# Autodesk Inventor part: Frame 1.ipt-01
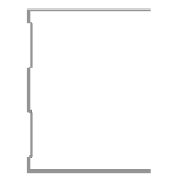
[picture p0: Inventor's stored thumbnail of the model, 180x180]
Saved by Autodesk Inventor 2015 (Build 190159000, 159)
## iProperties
Created: 2015-04
Part Number: Frame 1.ipt-01
Material: Aluminum 6061
Document SubType Name: Modeling
Standard: Unnamed
Designer: suporte
Language: en-US
Size Designation: (Unnamed 1)
Categories: <MemberInstance><Categories><Category DisplayName="Structural Shapes" InternalName="089c4875-fa83-4c05-b084-43b9cc11f5ed" Mnemonic="GRDR"><CategoryParameter Dis
Density: 2.7 g/cm^3
Appearance: Aluminum - Flat
IsCustomPart: 1
G_L: 2100,000 mm
G_W: 70,000 mm
G_H: 75,000 mm
_CCFamilyMember: 1
_CCFamilyDisplayName: Frame 1
_FrameMemberDoc: Frame Member File
_Version: 15.0.0
_GetPNFromCC: 1
Author: suporte
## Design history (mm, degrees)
node "Start Plane"
node "End Plane"
sketch "Sketch"
  geometry: L1 (34.6, 37.5)-(34.6, 36.7); L2 (34.6, 36.7)-(-34.6, 36.7); L3 (-34.6, -36.7)-(34.6, -36.7); L4 (34.6, -36.7)-(34.6, -37.5); L5 (34.6, -37.5)-(-35.4, -37.5); L6 (-35.4, 37.5)-(34.6, 37.5); L7 (-34.6, 36.7)-(-34.6, 31.7); L8 (-34.6, 31.7)-(-33.4, 30.5); L9 (-33.4, 30.5)-(-33.4, 10.746); L10 (-33.4, 10.746)-(-34.6, 9.546); L11 (-34.6, 9.546)-(-34.6, -9.546); L12 (-34.6, -9.546)-(-33.4, -10.746); L13 (-33.4, -10.746)-(-33.4, -30.5); L14 (-33.4, -30.5)-(-34.6, -31.7); L15 (-34.6, -31.7)-(-34.6, -36.7); L16 (-35.4, -37.5)-(-35.4, -31.369); L17 (-35.4, -31.369)-(-34.2, -30.169); L18 (-34.2, -30.169)-(-34.2, -11.077); L19 (-34.2, -11.077)-(-35.4, -9.877); L20 (-35.4, -9.877)-(-35.4, 9.877); L21 (-35.4, 9.877)-(-34.2, 11.077); L22 (-34.2, 11.077)-(-34.2, 30.169); L23 (-34.2, 30.169)-(-35.4, 31.369); L24 (-35.4, 31.369)-(-35.4, 37.5); L25 (-35.4, 0)-(30.37, 0); 3 further points
  constraints: 50 end point, 10 point on line, 9 parallel, 5 perpendicular, 4 equal length, 3 midpoint, 3 vertical, 2 vertical alignment, 1 collinear, 1 horizontal, 1 horizontal alignment
  dimensions: "d3" = 0.8 distance of L1.start L1.end; "d5" = 75 distance between parallel lines of L5 L6; "d6" = 0.8 distance between parallel lines of L24 L7; "d7" = 0.8 distance between parallel lines of L8 L23; "d8" = 0.8 distance between parallel lines of L22 L9; "d9" = 0.8 distance between parallel lines of L17 L14; "d10" = 0.8 distance between parallel lines of L13 L18; "d11" = 0.8 distance between parallel lines of L12 L19; "d12" = 0.8 distance between parallel lines of L21 L10; "d13" = 5 distance of L2.end L7.end; "d15" = 135 deg angle of L9 L8; "d16" = 2 distance between parallel lines of L24 L9; "d17" = 70 distance of L6.start L1.start
extrude "Body" join sketch "Sketch" stored distance "d24" = 0.13; taper "d25" = 0 deg
node "Driven Length"
  sketch "Sketch8"
    geometry: L1 (0, 0)-(10, 0) reference
    constraints: 2 end point, 1 horizontal
  workplane "Work Plane6"
  sketch "Sketch9"
    geometry: L1 (-2, 0)-(12, 0) reference; L2 (-2, 2100)-(12, 2100) reference
    dimensions: "d27" = 2100 distance between parallel lines of L1 L2 (derived)
body "Solid1"
other parameters: "G_OFFSET_START" = 0 [user parameter; used in 1 equation term], "G_OFFSET_END" = 0 [user parameter; used in 1 equation term], "d22" = 0 (computed from G_OFFSET_START), "G_L" = 2100 (= d27) [user parameter], "d32" = 90 deg
